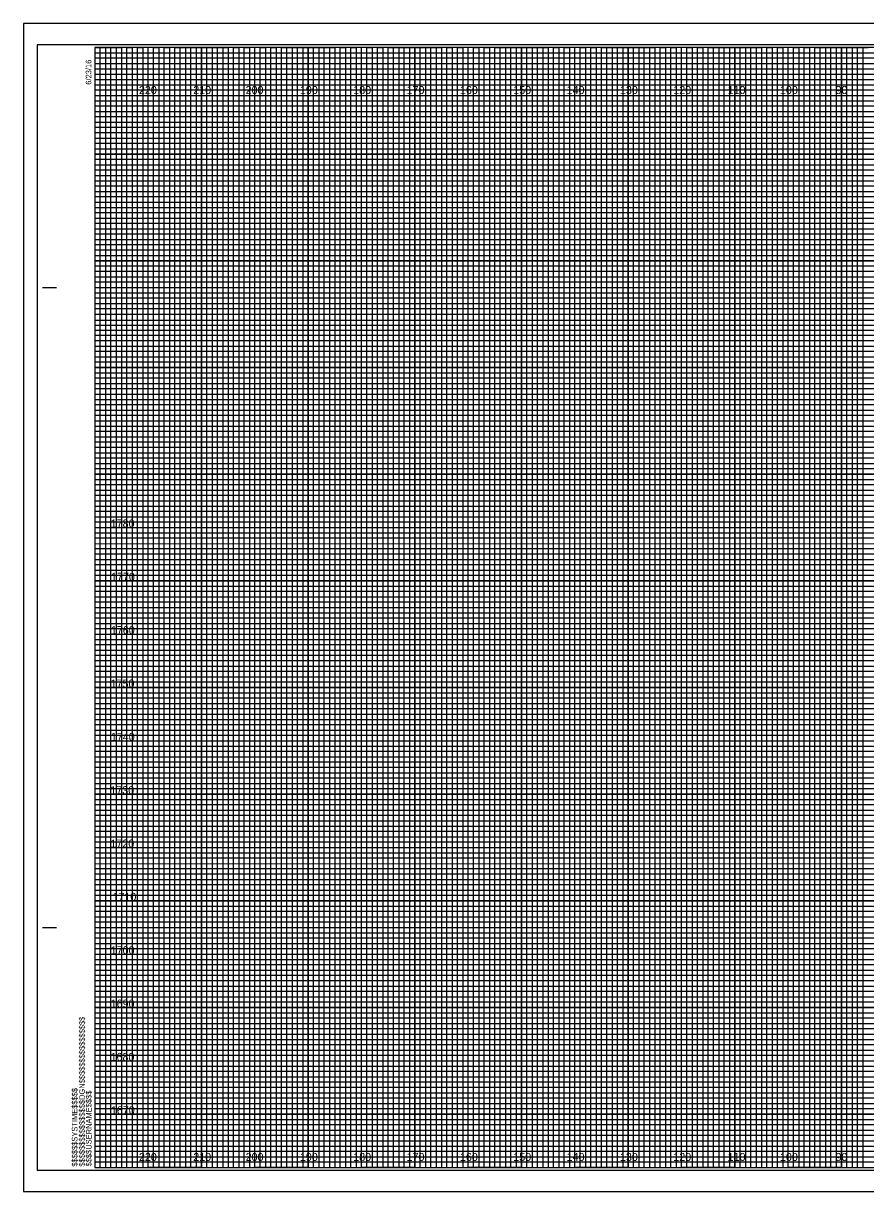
# Model space of a CAD drawing. Extents: x -419 to 4739, y -630 to 13534.
# Drawn here: x 3002 to 3159.9, y -28.1 to 190.9 of the extents above; entities that cross this region are included whole.
import ezdxf

# ---------------------------------------------------------------- set-up
doc = ezdxf.new("R2010")
doc.units = 0
for name, color, linetype in [('Old_Level_62', 7, 'Continuous'), ('Pattern 1', 7, 'Continuous'), ('Pattern 18', 7, 'Continuous'), ('Pattern 4', 7, 'Continuous'), ('Pattern 5', 7, 'Continuous'), ('Prop Dimension', 7, 'Continuous'), ('Prop Horizontal Alignment', 7, 'Continuous'), ('Raster_Level_0', 7, 'Continuous'), ('Scratch_Level_0', 7, 'Continuous'), ('Scratch_Level_3', 7, 'Continuous'), ('Scratch_Level_5', 7, 'Continuous')]:
    doc.layers.add(name, color=color, linetype=linetype)

msp = doc.modelspace()

# ---------------------------------------------------------------- linework, layer by layer
at = {"layer": 'Old_Level_62'}
for p, q in [((3005.59, 141.36), (3008.09, 141.36)), ((3005.69, 141.36), (3008.19, 141.36)), ((3005.59, 21.36), (3008.09, 21.36)), ((3005.69, 21.36), (3008.19, 21.36)), ((3015.39, -23.64), (3015.39, -23.64)), ((3015.39, -23.64), (3015.39, -23.64)), ((3015.39, -23.64), (3015.39, -23.64)), ((3015.39, -23.64), (3015.39, -23.64)), ((3015.39, -23.64), (3015.39, -23.64)), ((3015.39, -23.64), (3015.39, -23.64)), ((3015.39, -23.64), (3015.39, -23.64))]:
    msp.add_line(p, q, dxfattribs=at)
msp.add_lwpolyline([(3335.39, 186.36), (3015.39, 186.36), (3015.39, -23.64), (3335.39, -23.64)], close=True, dxfattribs=at)
at = {"layer": 'Pattern 18'}
msp.add_lwpolyline([(3001.99, -28.14), (3338.69, -28.14), (3338.69, 190.86), (3001.99, 190.86)], close=True, dxfattribs=at)
at = {"layer": 'Pattern 4'}
for p, q in [((3015.39, 185.36), (3275.39, 185.36)), ((3275.39, 184.34), (3015.39, 184.34)), ((3015.39, 184.34), (3015.39, 183.36)), ((3015.39, 183.36), (3275.39, 183.36)), ((3275.39, 182.25), (3015.39, 182.25)), ((3015.39, 182.25), (3015.39, 180.36)), ((3015.39, 180.36), (3335.39, 180.36))]:
    msp.add_line(p, q, dxfattribs=at)
for points in [[(3015.39, 179.36), (3285.39, 179.36), (3335.39, 179.36), (3335.39, 178.36), (3015.39, 178.36)], [(3015.39, 177.36), (3335.39, 177.36), (3335.39, 175.36), (3015.39, 175.36)], [(3015.39, 174.36), (3335.39, 174.36), (3335.39, 173.36), (3015.39, 173.34)], [(3015.39, 172.36), (3335.39, 172.36), (3335.39, 170.36), (3015.39, 170.36)], [(3015.39, 169.36), (3335.39, 169.36), (3335.39, 168.36), (3015.39, 168.36)], [(3015.39, 167.36), (3335.39, 167.36), (3335.39, 165.36), (3015.39, 165.36)], [(3015.39, 164.36), (3335.39, 164.36), (3335.39, 163.36), (3015.39, 163.36)], [(3015.39, 162.36), (3335.39, 162.36), (3335.39, 160.36), (3015.39, 160.36)], [(3015.39, 159.36), (3335.39, 159.36), (3335.39, 158.36), (3015.39, 158.36)], [(3015.39, 157.36), (3335.39, 157.36), (3335.39, 155.36), (3015.39, 155.36)], [(3015.39, 154.36), (3335.39, 154.36), (3335.39, 153.36), (3015.39, 153.36)], [(3015.39, 152.36), (3335.39, 152.36), (3335.39, 150.31), (3335.39, 149.36), (3335.39, 148.36), (3015.39, 148.36)], [(3015.39, 150.36), (3335.39, 150.36), (3335.39, 149.36), (3015.39, 149.36)], [(3015.39, 147.36), (3335.39, 147.36), (3335.39, 145.36), (3015.39, 145.39)], [(3015.39, 145.39), (3335.39, 145.36), (3335.39, 144.36), (3015.39, 144.36)], [(3015.39, 143.36), (3335.39, 143.36), (3335.39, 142.36), (3015.39, 142.36)], [(3015.39, 140.36), (3335.39, 140.36), (3335.39, 139.36), (3015.39, 139.36)], [(3015.39, 138.36), (3335.39, 138.36), (3335.39, 137.36), (3015.39, 137.36)], [(3015.32, 135.25), (3335.39, 135.25), (3335.39, 134.24), (3015.32, 134.24)], [(3015.39, 133.36), (3335.39, 133.36), (3335.39, 132.36), (3015.39, 132.36)], [(3015.39, 130.36), (3335.39, 130.36), (3335.39, 129.36), (3015.39, 129.36)], [(3015.39, 128.36), (3335.39, 128.36), (3335.39, 127.36), (3015.39, 127.36)], [(3015.39, 125.36), (3335.39, 125.36), (3335.39, 124.36), (3015.39, 124.36)], [(3015.39, 123.36), (3335.39, 123.36), (3335.39, 122.36), (3015.39, 122.36)], [(3015.39, 120.36), (3335.39, 120.36), (3335.39, 119.36), (3015.39, 119.36)], [(3015.39, 118.36), (3335.39, 118.36), (3335.39, 117.36), (3015.39, 117.36)], [(3015.39, 115.36), (3335.39, 115.36), (3335.38, 114.34), (3015.39, 114.36)], [(3015.39, 113.36), (3335.39, 113.36), (3335.39, 112.36), (3015.39, 112.36)], [(3015.39, 110.36), (3335.39, 110.36), (3335.39, 109.36), (3015.39, 109.36)], [(3015.39, 108.36), (3335.39, 108.36), (3335.39, 107.36), (3015.39, 107.36)], [(3015.39, 105.36), (3335.39, 105.36), (3335.39, 104.36), (3015.39, 104.36)], [(3015.39, 103.36), (3335.39, 103.36), (3335.39, 102.36), (3015.39, 102.36)], [(3015.39, 100.36), (3335.39, 100.36), (3335.39, 99.36), (3015.39, 99.36)], [(3015.39, 98.36), (3335.39, 98.36), (3335.39, 97.36), (3015.39, 97.36)], [(3015.39, 95.36), (3335.39, 95.36), (3335.39, 94.36), (3015.39, 94.36)], [(3015.39, 93.35), (3335.46, 93.27), (3335.39, 92.36), (3015.39, 92.36)], [(3015.39, 90.36), (3335.39, 90.36), (3335.39, 89.36), (3015.39, 89.36)], [(3015.39, 88.36), (3335.39, 88.36), (3335.39, 87.36), (3015.39, 87.36)], [(3015.39, 85.36), (3335.39, 85.36), (3335.39, 84.36), (3015.39, 84.36)], [(3015.39, 83.36), (3335.39, 83.36), (3335.39, 82.36), (3015.39, 82.36)], [(3015.39, 80.36), (3335.39, 80.36), (3335.39, 79.36), (3015.39, 79.36)], [(3015.39, 78.36), (3335.39, 78.36), (3335.39, 77.36), (3015.39, 77.36)], [(3015.39, 75.36), (3335.39, 75.36), (3335.39, 74.36), (3015.39, 74.36)], [(3015.39, 73.36), (3335.39, 73.36), (3335.39, 72.36), (3015.39, 72.36)], [(3015.39, 70.36), (3335.39, 70.36), (3335.39, 69.36), (3015.39, 69.36)], [(3015.39, 68.36), (3335.39, 68.36), (3335.39, 67.36), (3015.39, 67.36)], [(3015.39, 65.36), (3335.39, 65.36), (3335.39, 64.36), (3015.39, 64.36)], [(3015.39, 63.36), (3335.39, 63.36), (3335.39, 62.36), (3015.39, 62.36)], [(3015.39, 60.36), (3335.39, 60.36), (3335.39, 59.36), (3015.39, 59.36)], [(3015.39, 58.36), (3335.39, 58.36), (3335.39, 57.36), (3015.39, 57.36)], [(3015.39, 55.36), (3335.39, 55.36), (3335.38, 54.34), (3015.39, 54.36)], [(3015.39, 53.36), (3335.39, 53.36), (3335.39, 52.36), (3015.39, 52.36)], [(3015.39, 50.36), (3335.39, 50.36), (3335.39, 49.36), (3015.39, 49.36)], [(3015.39, 48.36), (3335.39, 48.36), (3335.39, 47.36), (3015.39, 47.36)], [(3015.39, 45.36), (3335.39, 45.36), (3335.39, 44.36), (3015.39, 44.36)], [(3015.39, 43.36), (3335.39, 43.36), (3335.39, 42.36), (3015.39, 42.36)], [(3015.39, 40.36), (3335.39, 40.36), (3335.39, 39.36), (3015.39, 39.36)], [(3015.39, 38.36), (3335.39, 38.36), (3335.39, 37.36), (3015.39, 37.36)], [(3015.39, 35.36), (3335.39, 35.36), (3335.39, 34.36), (3015.39, 34.36)], [(3015.39, 33.35), (3335.46, 33.27), (3335.39, 32.36), (3015.39, 32.36)], [(3015.39, 30.36), (3335.39, 30.36), (3335.39, 29.36), (3015.39, 29.36)], [(3015.39, 28.36), (3335.39, 28.36), (3335.39, 27.36), (3015.39, 27.36)], [(3015.39, 25.36), (3335.39, 25.36), (3335.39, 24.36), (3015.39, 24.36)], [(3015.39, 23.36), (3335.39, 23.36), (3335.39, 22.36), (3015.39, 22.36)], [(3015.39, 20.36), (3335.39, 20.36), (3335.39, 19.36), (3015.39, 19.36)], [(3015.39, 18.36), (3335.39, 18.36), (3335.39, 17.36), (3015.39, 17.36)], [(3015.39, 15.36), (3335.39, 15.36), (3335.39, 14.36), (3015.39, 14.36)], [(3015.39, 13.36), (3335.39, 13.36), (3335.39, 12.36), (3015.39, 12.36)], [(3015.39, 10.36), (3335.39, 10.36), (3335.39, 9.36), (3015.39, 9.36)], [(3015.39, 8.36), (3335.39, 8.36), (3335.39, 7.36), (3015.39, 7.36)], [(3015.39, 5.36), (3335.39, 5.36), (3335.39, 4.36), (3015.39, 4.36)], [(3015.39, 3.36), (3335.39, 3.36), (3335.39, 2.36), (3015.39, 2.36)], [(3015.39, 0.36), (3335.39, 0.36), (3335.39, -0.64), (3015.39, -0.64)], [(3015.39, -1.64), (3335.39, -1.64), (3335.39, -2.64), (3015.39, -2.64)], [(3015.39, -4.64), (3335.39, -4.64), (3335.39, -5.64), (3015.39, -5.64)], [(3015.39, -6.64), (3335.39, -6.64), (3335.39, -7.64), (3015.39, -7.64)], [(3015.39, -9.64), (3335.39, -9.64), (3335.39, -10.64), (3015.39, -10.64)], [(3015.39, -11.64), (3335.39, -11.64), (3335.39, -12.64), (3015.39, -12.64)], [(3015.39, -14.64), (3335.39, -14.64), (3335.39, -15.64), (3015.39, -15.64)], [(3015.39, -16.64), (3335.39, -16.64), (3335.39, -17.64), (3015.39, -17.64)], [(3015.39, -19.64), (3335.39, -19.64), (3335.39, -20.64), (3015.39, -20.64)], [(3015.39, -21.64), (3335.39, -21.64), (3335.39, -22.64), (3015.39, -22.64)]]:
    msp.add_lwpolyline(points, dxfattribs=at)
at = {"layer": 'Pattern 5'}
for p, q in [((3338.69, 190.86), (3001.99, 190.86)), ((3001.99, 190.86), (3001.99, -28.14)), ((3001.99, -28.14), (3338.69, -28.14))]:
    msp.add_line(p, q, dxfattribs=at)
at = {"layer": 'Prop Dimension'}
for points in [[(3015.39, -23.64), (3016.39, -23.64), (3016.39, 186.36), (3017.39, 186.36), (3017.39, -23.64)], [(3017.39, -23.64), (3018.39, -23.64), (3018.39, 186.36), (3019.39, 186.36), (3019.39, -23.64)], [(3020.39, -23.64), (3021.39, -23.64), (3021.39, 186.36), (3022.39, 186.36), (3022.39, -23.64)], [(3022.39, -23.64), (3023.39, -23.64), (3023.39, 186.36), (3024.39, 186.36), (3024.39, -23.64)], [(3025.39, -23.64), (3026.39, -23.64), (3026.39, 186.36), (3027.39, 186.36), (3027.39, -23.64)], [(3027.39, -23.64), (3028.39, -23.64), (3028.39, 186.36), (3029.39, 186.36), (3029.39, -23.64)], [(3030.39, -23.64), (3031.39, -23.64), (3031.39, 186.36), (3032.39, 186.36), (3032.39, -23.64)], [(3032.39, -23.64), (3033.39, -23.64), (3033.39, 186.36), (3034.39, 186.36), (3034.39, -23.64)], [(3035.39, -23.64), (3036.39, -23.64), (3036.39, 186.36), (3037.39, 186.36), (3037.39, -23.64)], [(3037.39, -23.64), (3038.39, -23.64), (3038.39, 186.36), (3039.39, 186.36), (3039.39, -23.64)], [(3040.39, -23.64), (3041.39, -23.64), (3041.39, 186.36), (3042.39, 186.36), (3042.39, -23.64)], [(3042.39, -23.64), (3043.39, -23.64), (3043.39, 186.36), (3044.39, 186.36), (3044.39, -23.64)], [(3045.39, -23.64), (3046.39, -23.64), (3046.39, 186.36), (3047.39, 186.36), (3047.39, -23.64)], [(3047.39, -23.64), (3048.39, -23.64), (3048.39, 186.36), (3049.39, 186.36), (3049.39, -23.64)], [(3050.39, -23.64), (3051.39, -23.64), (3051.39, 186.36), (3052.39, 186.36), (3052.39, -23.64)], [(3052.39, -23.64), (3053.39, -23.64), (3053.39, 186.36), (3054.39, 186.36), (3054.39, -23.64)], [(3055.39, -23.64), (3056.39, -23.64), (3056.39, 186.36), (3057.39, 186.36), (3057.39, -23.64)], [(3057.39, -23.64), (3058.39, -23.64), (3058.39, 186.36), (3059.39, 186.36), (3059.39, -23.64)], [(3060.39, -23.64), (3061.39, -23.64), (3061.39, 186.36), (3062.39, 186.36), (3062.39, -23.64)], [(3062.39, -23.64), (3063.39, -23.64), (3063.39, 186.36), (3064.39, 186.36), (3064.39, -23.64)], [(3065.39, -23.64), (3066.39, -23.64), (3066.39, 186.36), (3067.39, 186.36), (3067.39, -23.64)], [(3067.39, -23.64), (3068.39, -23.64), (3068.39, 186.36), (3069.39, 186.36), (3069.39, -23.64)], [(3070.39, -23.64), (3071.39, -23.64), (3071.39, 186.36), (3072.39, 186.36), (3072.39, -23.64)], [(3072.39, -23.64), (3073.39, -23.64), (3073.39, 186.36), (3074.39, 186.36), (3074.39, -23.64)], [(3075.39, -23.64), (3076.39, -23.64), (3076.39, 186.36), (3077.39, 186.36), (3077.39, -23.64)], [(3077.39, -23.64), (3078.39, -23.64), (3078.39, 186.36), (3079.39, 186.36), (3079.39, -23.64)], [(3080.39, -23.64), (3081.39, -23.64), (3081.39, 186.36), (3082.39, 186.36), (3082.39, -23.64)], [(3082.39, -23.64), (3083.39, -23.64), (3083.39, 186.36), (3084.39, 186.36), (3084.39, -23.64)], [(3085.39, -23.64), (3086.39, -23.64), (3086.39, 186.36), (3087.39, 186.36), (3087.39, -23.64)], [(3087.39, -23.64), (3088.39, -23.64), (3088.39, 186.36), (3089.39, 186.36), (3089.39, -23.64)], [(3090.39, -23.64), (3091.39, -23.64), (3091.39, 186.36), (3092.39, 186.36), (3092.39, -23.64)], [(3092.39, -23.64), (3093.39, -23.64), (3093.39, 186.36), (3094.39, 186.36), (3094.39, -23.64)], [(3095.39, -23.64), (3096.39, -23.64), (3096.39, 186.36), (3097.39, 186.36), (3097.39, -23.64)], [(3097.39, -23.64), (3098.39, -23.64), (3098.39, 186.36), (3099.39, 186.36), (3099.39, -23.64)], [(3100.39, -23.64), (3101.39, -23.64), (3101.39, 186.36), (3102.39, 186.36), (3102.39, -23.64)], [(3102.39, -23.64), (3103.39, -23.64), (3103.39, 186.36), (3104.39, 186.36), (3104.39, -23.64)], [(3105.39, -23.64), (3106.39, -23.64), (3106.39, 186.36), (3107.39, 186.36), (3107.39, -23.64)], [(3107.39, -23.64), (3108.39, -23.64), (3108.39, 186.36), (3109.39, 186.36), (3109.39, -23.64)], [(3110.39, -23.64), (3111.39, -23.64), (3111.39, 186.36), (3112.39, 186.36), (3112.39, -23.64)], [(3112.39, -23.64), (3113.39, -23.64), (3113.39, 186.36), (3114.39, 186.36), (3114.39, -23.64)], [(3115.39, -23.64), (3116.39, -23.64), (3116.39, 186.36), (3117.39, 186.36), (3117.39, -23.64)], [(3117.39, -23.64), (3118.39, -23.64), (3118.39, 186.36), (3119.39, 186.36), (3119.39, -23.64)], [(3120.39, -23.64), (3121.39, -23.64), (3121.39, 186.36), (3122.39, 186.36), (3122.39, -23.64)], [(3122.39, -23.64), (3123.39, -23.64), (3123.39, 186.36), (3124.39, 186.36), (3124.39, -23.64)], [(3125.39, -23.64), (3126.39, -23.64), (3126.39, 186.36), (3127.39, 186.36), (3127.39, -23.64)], [(3127.39, -23.64), (3128.39, -23.64), (3128.39, 186.36), (3129.39, 186.36), (3129.39, -23.64)], [(3130.39, -23.64), (3131.39, -23.64), (3131.39, 186.36), (3132.39, 186.36), (3132.39, -23.64)], [(3132.39, -23.64), (3133.39, -23.64), (3133.39, 186.36), (3134.39, 186.36), (3134.39, -23.64)], [(3135.39, -23.64), (3136.39, -23.64), (3136.39, 186.36), (3137.39, 186.36), (3137.39, -23.64)], [(3137.39, -23.64), (3138.39, -23.64), (3138.39, 186.36), (3139.39, 186.36), (3139.39, -23.64)], [(3140.39, -23.64), (3141.39, -23.64), (3141.39, 186.36), (3142.39, 186.36), (3142.39, -23.64)], [(3142.39, -23.64), (3143.39, -23.64), (3143.39, 186.36), (3144.39, 186.36), (3144.39, -23.64)], [(3145.39, -23.64), (3146.39, -23.64), (3146.39, 186.36), (3147.39, 186.36), (3147.39, -23.64)], [(3147.39, -23.64), (3148.39, -23.64), (3148.39, 186.36), (3149.39, 186.36), (3149.39, -23.64)], [(3150.39, -23.64), (3151.39, -23.64), (3151.39, 186.36), (3152.39, 186.36), (3152.39, -23.64)], [(3152.39, -23.64), (3153.39, -23.64), (3153.39, 186.36), (3154.39, 186.36), (3154.39, -23.64)], [(3155.39, -23.64), (3156.39, -23.64), (3156.39, 186.36), (3157.39, 186.36), (3157.39, -23.64)], [(3157.39, -23.64), (3158.39, -23.64), (3158.39, 186.36), (3159.39, 186.36), (3159.39, -23.64)]]:
    msp.add_lwpolyline(points, dxfattribs=at)
at = {"layer": 'Prop Horizontal Alignment'}
for points in [[(3015.39, 186.36), (3020.39, 186.36), (3020.39, -23.64), (3030.39, -23.64), (3030.39, 186.36), (3040.39, 186.36), (3040.39, -23.64), (3050.39, -23.64), (3050.39, 186.36), (3060.39, 186.36), (3060.39, -23.64), (3070.39, -23.64), (3070.39, 186.36), (3080.39, 186.36), (3080.39, -23.64), (3090.39, -23.64), (3090.39, 186.36), (3100.39, 186.36), (3100.39, -23.64), (3110.39, -23.64), (3110.39, 186.36), (3120.39, 186.36), (3120.39, -23.64), (3130.39, -23.64), (3130.39, 186.36), (3140.39, 186.36), (3140.39, -23.64), (3150.39, -23.64), (3150.39, 186.36), (3160.39, 186.36)], [(3015.39, 181.36), (3290.39, 181.36)], [(3015.39, 161.36), (3335.39, 161.36), (3335.39, 171.36), (3015.39, 171.36)], [(3015.39, 141.36), (3335.39, 141.36), (3335.39, 151.36), (3015.39, 151.36)], [(3015.39, 121.36), (3335.39, 121.36), (3335.39, 131.36), (3015.39, 131.36)], [(3015.39, 101.36), (3335.39, 101.36), (3335.39, 111.36), (3015.39, 111.36)], [(3015.39, 81.36), (3335.39, 81.36), (3335.39, 91.36), (3015.39, 91.36)], [(3015.39, 61.36), (3335.39, 61.36), (3335.39, 71.36), (3015.39, 71.36)], [(3015.39, 41.36), (3335.39, 41.36), (3335.39, 51.36), (3015.39, 51.36)], [(3015.39, 21.36), (3335.39, 21.36), (3335.39, 31.36), (3015.39, 31.36)], [(3015.39, 1.36), (3335.39, 1.36), (3335.39, 11.36), (3015.39, 11.36)], [(3015.39, -18.64), (3335.39, -18.64), (3335.39, -8.64), (3015.39, -8.64)]]:
    msp.add_lwpolyline(points, dxfattribs=at)
at = {"layer": 'Scratch_Level_0'}
for p, q in [((3025.39, -23.64), (3025.39, 186.36)), ((3035.39, -23.64), (3035.39, 186.36)), ((3045.39, -23.64), (3045.39, 186.36)), ((3055.39, -23.64), (3055.39, 186.36)), ((3065.39, -23.64), (3065.39, 186.36)), ((3075.39, -23.64), (3075.39, 186.36)), ((3085.39, -23.64), (3085.39, 186.36)), ((3095.39, -23.64), (3095.39, 186.36)), ((3105.39, -23.64), (3105.39, 186.36)), ((3115.39, -23.64), (3115.39, 186.36)), ((3125.39, -23.64), (3125.39, 186.36)), ((3135.39, -23.64), (3135.39, 186.36)), ((3145.39, -23.64), (3145.39, 186.36)), ((3155.39, -23.64), (3155.39, 186.36)), ((3015.39, 176.36), (3335.39, 176.36)), ((3015.39, 166.36), (3335.39, 166.36)), ((3015.39, 156.36), (3335.39, 156.36)), ((3015.39, 146.36), (3335.39, 146.36)), ((3015.39, 136.36), (3335.39, 136.36)), ((3015.39, 126.36), (3335.39, 126.36)), ((3015.39, 116.36), (3335.39, 116.36)), ((3015.39, 106.36), (3335.39, 106.36)), ((3015.39, 96.36), (3335.39, 96.36)), ((3015.39, 86.36), (3335.39, 86.36)), ((3015.39, 76.36), (3335.39, 76.36)), ((3015.39, 66.36), (3335.39, 66.36)), ((3015.39, 56.36), (3335.39, 56.36)), ((3015.39, 46.36), (3335.39, 46.36)), ((3015.39, 36.36), (3335.39, 36.36)), ((3015.39, 26.36), (3335.39, 26.36)), ((3015.39, 16.36), (3335.39, 16.36)), ((3015.39, 6.36), (3335.39, 6.36)), ((3015.39, -3.64), (3335.39, -3.64)), ((3015.39, -13.64), (3335.39, -13.64))]:
    msp.add_line(p, q, dxfattribs=at)
at = {"layer": 'Scratch_Level_3'}
for p, q in [((3025.39, 186.36), (3015.39, 186.36)), ((3025.39, -23.64), (3025.39, 186.36)), ((3045.39, 186.36), (3035.39, 186.36)), ((3035.39, 186.36), (3035.39, -23.64)), ((3045.39, -23.64), (3045.39, 186.36)), ((3065.39, 186.36), (3055.39, 186.36)), ((3055.39, 186.36), (3055.39, -23.64)), ((3065.39, -23.64), (3065.39, 186.36)), ((3085.39, 186.36), (3075.39, 186.36)), ((3075.39, 186.36), (3075.39, -23.64)), ((3085.39, -23.64), (3085.39, 186.36)), ((3105.39, 186.36), (3095.39, 186.36)), ((3095.39, 186.36), (3095.39, -23.64)), ((3105.39, -23.64), (3105.39, 186.36)), ((3125.39, 186.36), (3115.39, 186.36)), ((3115.39, 186.36), (3115.39, -23.64)), ((3125.39, -23.64), (3125.39, 186.36)), ((3145.39, 186.36), (3135.39, 186.36)), ((3135.39, 186.36), (3135.39, -23.64)), ((3145.39, -23.64), (3145.39, 186.36)), ((3165.39, 186.36), (3155.39, 186.36)), ((3155.39, 186.36), (3155.39, -23.64)), ((3035.39, -23.64), (3025.39, -23.64)), ((3055.39, -23.64), (3045.39, -23.64)), ((3075.39, -23.64), (3065.39, -23.64)), ((3095.39, -23.64), (3085.39, -23.64)), ((3115.39, -23.64), (3105.39, -23.64)), ((3135.39, -23.64), (3125.39, -23.64)), ((3155.39, -23.64), (3145.39, -23.64))]:
    msp.add_line(p, q, dxfattribs=at)
for points in [[(3015.39, 176.36), (3335.39, 176.36), (3335.39, 166.36), (3015.39, 166.36)], [(3015.39, 156.36), (3335.39, 156.36), (3335.39, 146.36), (3015.39, 146.36)], [(3015.39, 136.36), (3335.39, 136.36), (3335.39, 126.36), (3015.39, 126.36)], [(3015.39, 116.36), (3335.39, 116.36), (3335.39, 106.36), (3015.39, 106.36)], [(3015.39, 96.36), (3335.39, 96.36), (3335.39, 86.36), (3015.39, 86.36)], [(3015.39, 76.36), (3335.39, 76.36), (3335.39, 66.36), (3015.39, 66.36)], [(3015.39, 56.36), (3335.39, 56.36), (3335.39, 46.36), (3015.39, 46.36)], [(3015.39, 36.36), (3335.39, 36.36), (3335.39, 26.36), (3015.39, 26.36)], [(3015.39, 16.36), (3335.39, 16.36), (3335.39, 6.36), (3015.39, 6.36)], [(3015.39, -3.64), (3335.39, -3.64), (3335.39, -13.64), (3015.39, -13.64)]]:
    msp.add_lwpolyline(points, dxfattribs=at)
at = {"layer": 'Scratch_Level_5'}
msp.add_lwpolyline([(3004.59, -24.14), (3337.79, -24.14), (3337.79, 186.86), (3004.59, 186.86)], close=True, dxfattribs=at)

# ---------------------------------------------------------------- texts
at = {"layer": 'Old_Level_62'}
for s, p in [('6/23/16', (3014.74, 179.36)), ('$$$$$$$$$$$$$$$$DGN$$$$$$$$$$$$$$$$', (3013.51, -23.46)), ('$$$$$$SYSTIME$$$$$', (3012.13, -23.46)), ('$$$$USERNAME$$$$', (3014.77, -23.41))]:
    msp.add_text(s, height=1.05, rotation=90, dxfattribs=at).set_placement(p)
at = {"layer": 'Pattern 1'}
for s, p in [('1780', (3018.37, 96.36)), ('1770', (3018.43, 86.36)), ('1760', (3018.4, 76.36)), ('1750', (3018.35, 66.36)), ('1740', (3018.4, 56.36)), ('1730', (3018.31, 46.36)), ('1720', (3018.32, 36.36)), ('1710', (3018.7, 26.36)), ('1700', (3018.37, 16.36)), ('1690', (3018.36, 6.36)), ('1680', (3018.34, -3.64)), ('1670', (3018.4, -13.64))]:
    msp.add_text(s, height=1.5, dxfattribs=at).set_placement(p)
at = {"layer": 'Raster_Level_0'}
for s, p in [('220', (3023.66, 177.61)), ('210', (3033.84, 177.61)), ('200', (3043.66, 177.61)), ('190', (3053.84, 177.61)), ('180', (3063.84, 177.61)), ('170', (3073.84, 177.61)), ('160', (3083.84, 177.61)), ('150', (3093.84, 177.61)), ('140', (3103.84, 177.61)), ('130', (3113.84, 177.61)), ('120', (3123.84, 177.61)), ('110', (3134.02, 177.61)), ('100', (3143.84, 177.61)), ('90', (3154.25, 177.61)), ('220', (3023.66, -22.39)), ('210', (3033.84, -22.39)), ('200', (3043.66, -22.39)), ('190', (3053.84, -22.39)), ('180', (3063.84, -22.39)), ('170', (3073.84, -22.39)), ('160', (3083.84, -22.39)), ('150', (3093.84, -22.39)), ('140', (3103.84, -22.39)), ('130', (3113.84, -22.39)), ('120', (3123.84, -22.39)), ('110', (3134.02, -22.39)), ('100', (3143.84, -22.39)), ('90', (3154.25, -22.39))]:
    msp.add_text(s, height=1.5, dxfattribs=at).set_placement(p)

doc.saveas('drawing.dxf')
